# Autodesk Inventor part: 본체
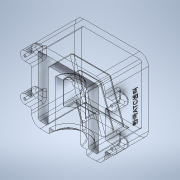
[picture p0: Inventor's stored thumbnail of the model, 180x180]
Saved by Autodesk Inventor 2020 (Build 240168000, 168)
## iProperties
Created: 2022-03
Part Number: 본체
Material: 일반
Document SubType Name: Modeling
Designer: Administrator
Density: 1 g/cm^3
Appearance: 기본값
Mass: 379.39 g
Surface Area: 845.158 cm^2
Volume: 379.39 cm^3
Author: Administrator
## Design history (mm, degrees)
sketch "스케치1"
  geometry: L1 (-55, -55)-(55, -55); L2 (55, -55)-(55, 55); L3 (55, 55)-(-55, 55); L4 (-55, 55)-(-55, -55); L5 (-55, -55)-(55, 55); L6 (55, -55)-(-55, 55); 1 further point
  constraints: 12 end point, 2 midpoint, 2 parallel, 1 horizontal, 1 perpendicular
  dimensions: "d0" = 110 distance of L2.end L3.end; "d1" = 110 distance of L1.end L2.end
extrude "돌출1" new body sketch "스케치1" stored distance "d2" = 65; taper "d3" = 0 deg
sketch "스케치2"
  geometry: L1 (0, 0)-(110, 0) reference; C1 r 28 at (55, 0); 1 further point
  constraints: 1 centre point, 1 midpoint
  dimensions: "d4" = 56 diameter of C1
extrude "돌출2" cut sketch "스케치2" distance "d5" = 8; taper "d6" = 0 deg
sketch "스케치3"
  geometry: C1 r 19 at (55, 0); A1 r 28 centre (55, 0) between (27, 0) and (83, 0) reference; 1 further point
  constraints: 1 centre point, 1 coincident
  dimensions: "d7" = 38 diameter of C1
extrude "돌출3" cut sketch "스케치3" distance "d8" = 72; taper "d9" = 0 deg
sketch "스케치4"
  geometry: L1 (36, 0)-(74, 0) reference; C1 r 7.5 at (55, 0); A1 r 19 centre (55, 0) between (36, 0) and (74, 0) reference; 1 further point
  constraints: 1 centre point, 1 coincident
  dimensions: "d10" = 15 diameter of C1
extrude "돌출4" cut sketch "스케치4" distance "d11" = 4; taper "d12" = -30 deg
sketch "스케치5"
  geometry: A1 r 5.191 centre (55, 0) between (49.809, 0) and (60.191, 0) reference; 2 further points
  constraints: 1 vertical alignment
  dimensions: "d13" = 23 distance of point (55, -23) A1.centre
hole "구멍1" sketch "스케치5" at (55, -23) diameter "d14" = 3.242; stored, may be unused: countersink angle "d18" = 90 deg, drill point angle "d20" = 118 deg; dims "d15" = 9, "d16" = 4, "d17" = 2, "d19" = 11
fillet "모깎기1" dims "d21" = 1
chamfer "모따기1" distance "d22" = 1; stored, may be unused: second distance "d23" = 2, angle "d24" = 45 deg
sketch "스케치7"
  geometry: L1 (-45, 45)-(-45, -45); L2 (-45, -45)-(-30, -45); L3 (-30, -45)-(-30, 33); L4 (-30, 33)-(30, 33); L5 (30, 33)-(30, -45); L6 (30, -45)-(45, -45); L7 (45, -45)-(45, 45); L8 (45, 45)-(-45, 45); L9 (29, -55)-(55, -55) reference; L10 (55, -55)-(55, 55) reference; L11 (-55, 55)-(-55, -55) reference; L12 (55, 55)-(-55, 55) reference; 1 further point
  constraints: 16 end point, 5 perpendicular, 2 point on line, 2 vertical
  dimensions: "d25" = 10 distance between parallel lines of L9 L6; "d26" = 10 distance between parallel lines of L10 L7; "d27" = 10 distance between parallel lines of L11 L1; "d28" = 10 distance between parallel lines of L12 L8; "d29" = 25 distance between parallel lines of L10 L5; "d30" = 22 distance between parallel lines of L12 L4; "d31" = 25 distance between parallel lines of L11 L3
extrude "돌출5" cut sketch "스케치7" extent not by distance; stored distance "d32" = 0; taper "d33" = 0 deg
sketch "스케치10"
  geometry: L1 (19, 23)-(-19, 23); L2 (-19, 23)-(-19, 6.343); L3 (-19, 6.343)-(-55, -3.303); L4 (19, 23)-(19, -1.075); L5 (19, -1.075)-(-55, -20.903); L6 (-55, 32.5)-(-55, 3.5) reference; L7 (-55, 32.5)-(-55, 32.5) reference; L8 (-55, 32.5)-(-55, -32.5) reference; L9 (-55, -32.5)-(-55, 32.5) reference; L10 (-46, 13.5)-(24, 13.5) reference; L11 (24, 32.5)-(24, 13.5) reference; L12 (33, -2.5)-(-40.778, -22.269); L13 (33, 32.5)-(33, -32.5) reference; L14 (33, -32.5)-(-45, -32.5) reference; 7 further points
  constraints: 12 end point, 3 point on line, 2 midpoint, 2 parallel, 1 horizontal, 1 horizontal alignment, 1 perpendicular, 1 vertical
  dimensions: "d37" = 17 distance between parallel lines of L5 L3; "d38" = 38 distance between parallel lines of L2 L4; "d39" = 36 distance between parallel lines of L6 L2; "d40" = 30 distance from line of L14 L12.start; "d41" = 75 deg angle of L12 L13; "d42" = 5 distance between parallel lines of L5 L12
extrude "돌출6" cut sketch "스케치10" stored distance "d43" = 34; taper "d44" = 0 deg
fillet "모깎기2" dims "d45" = 3
fillet "모깎기3" dims "d46" = 3
sketch "스케치11"
  geometry: L1 (33, -2.5)-(-38.903, -21.766); L2 (33, 32.5)-(33, -32.5) reference; L3 (33, -32.5)-(-45, -32.5) reference; L4 (-38.903, -21.766)-(-45, -23.4); L5 (-45, -23.4)-(-45, -32.5); L6 (-55, -32.5)-(-55, 32.5) reference; 1 further point
  constraints: 6 end point, 3 point on line, 1 perpendicular
  dimensions: "d50" = 30 distance from line of L3 L1.start; "d51" = 75 deg angle of L1 L2; "d71" = 10 distance between parallel lines of L6 L5
extrude "돌출7" cut sketch "스케치11" stored distance "d52" = 60; taper "d53" = 0 deg
fillet "모깎기7" dims "d54" = 3
fillet "모깎기8" dims "d55" = 3
fillet "모깎기9" dims "d56" = 13
sketch "스케치12"
  geometry: L1 (42, 55)-(-42, 55) reference; L2 (0, 0)-(0, 9.926); L3 (-65, 35)-(-55, 35); L4 (-55, 42)-(-55, -42) reference; L5 (-65, -21)-(-55, -21); L6 (-65, 21)-(-55, 21); L7 (-65, -35)-(-55, -35); L8 (65, 21)-(55, 21); L9 (65, 35)-(55, 35); L10 (65, -21)-(55, -21); L11 (65, -35)-(55, -35); L12 (55, 35)-(55, 21); L13 (55, 42)-(55, -42) reference; L14 (55, -21)-(55, -35); A1 r 7 centre (-65, -28) between (-65, -21) and (-65, -35); A2 r 7 centre (-65, 28) between (-65, 35) and (-65, 21); A3 r 7 centre (65, 28) between (65, 21) and (65, 35); A4 r 7 centre (65, -28) between (65, -35) and (65, -21)
  constraints: 22 end point, 10 symmetric about line, 8 point on circle, 4 centre point, 4 point on line, 4 tangent, 3 perpendicular, 2 collinear, 1 equal radius, 1 horizontal, 1 vertical, 1 vertical alignment, 2 other
  dimensions: "d57" = 14 diameter of A2; "d58" = 56 distance of A1.centre A2.centre; "d59" = 27 distance from line of L1 A2.centre; "d60" = 65 horizontal distance of L2.start A2.centre
extrude "돌출8" join sketch "스케치12" distance "d61" = 20; taper "d62" = 0 deg
sketch "스케치13"
  geometry: A1 r 7 centre (-65, 28) between (-65, 35) and (-65, 21) reference; A2 r 7 centre (-65, -28) between (-65, -21) and (-65, -35) reference; A3 r 7 centre (65, 28) between (65, 21) and (65, 35) reference; A4 r 7 centre (65, -28) between (65, -35) and (65, -21) reference; 5 further points
  constraints: 4 coincident
hole "구멍2" sketch "스케치13" at (-65, 28), (-65, -28), (65, 28), (65, -28) diameter "d63" = 3.242; stored, may be unused: countersink angle "d67" = 90 deg, drill point angle "d69" = 118 deg; dims "d64" = 9, "d65" = 4, "d66" = 2, "d68" = 11
fillet "모깎기10" dims "d72" = 3
sketch "스케치14"
  geometry: L1 (0, 84)-(0, 0) reference; L2 (-65, -13)-(0, -13) reference; 2 further points
  constraints: 1 other
  dimensions: "d73" = 20 distance from line of L1 point (-20, 42); "d74" = 55 distance from line of L2 point (-20, 42)
feature "엠보싱1" sketch "스케치14" dims "d0" = 110, "d1" = 110, "d75" = 0.5, "d76" = 0
fillet "모깎기11" dims "d77" = 3
fillet "모깎기12" dims "d78" = 1
fillet "모깎기13" dims "d79" = 3
fillet "모깎기14" dims "d80" = 3
fillet "모깎기15" dims "d81" = 3
fillet "모깎기16" dims "d82" = 3
fillet "모깎기17" dims "d83" = 3
fillet "모깎기18" dims "d84" = 3
node "솔리드1"
node "투영된 루프1"
node "투영된 루프2"
feature "A9D066F2-1C7D-4E18-AEED-F7BC21143FA4" dims "d14" = 3.242, "d15" = 9, "d16" = 4, "d17" = 2, "d18" = 90 deg, "d19" = 11, "d20" = 118 deg
